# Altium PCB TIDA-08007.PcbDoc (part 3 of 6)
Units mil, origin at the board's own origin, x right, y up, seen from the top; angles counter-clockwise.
Board outline 4212.6 x 2047.24 mil, 10 copper layers (Top Layer, GND 1, Signal Layer 1, GND 2, Split PWR 1, Split PWR 2, GND 3, Signal Layer 2, GND 4, Bottom Layer), stack 66.4 mil thick; 291 components, 178 nets, 1281 pads, 873 vias.
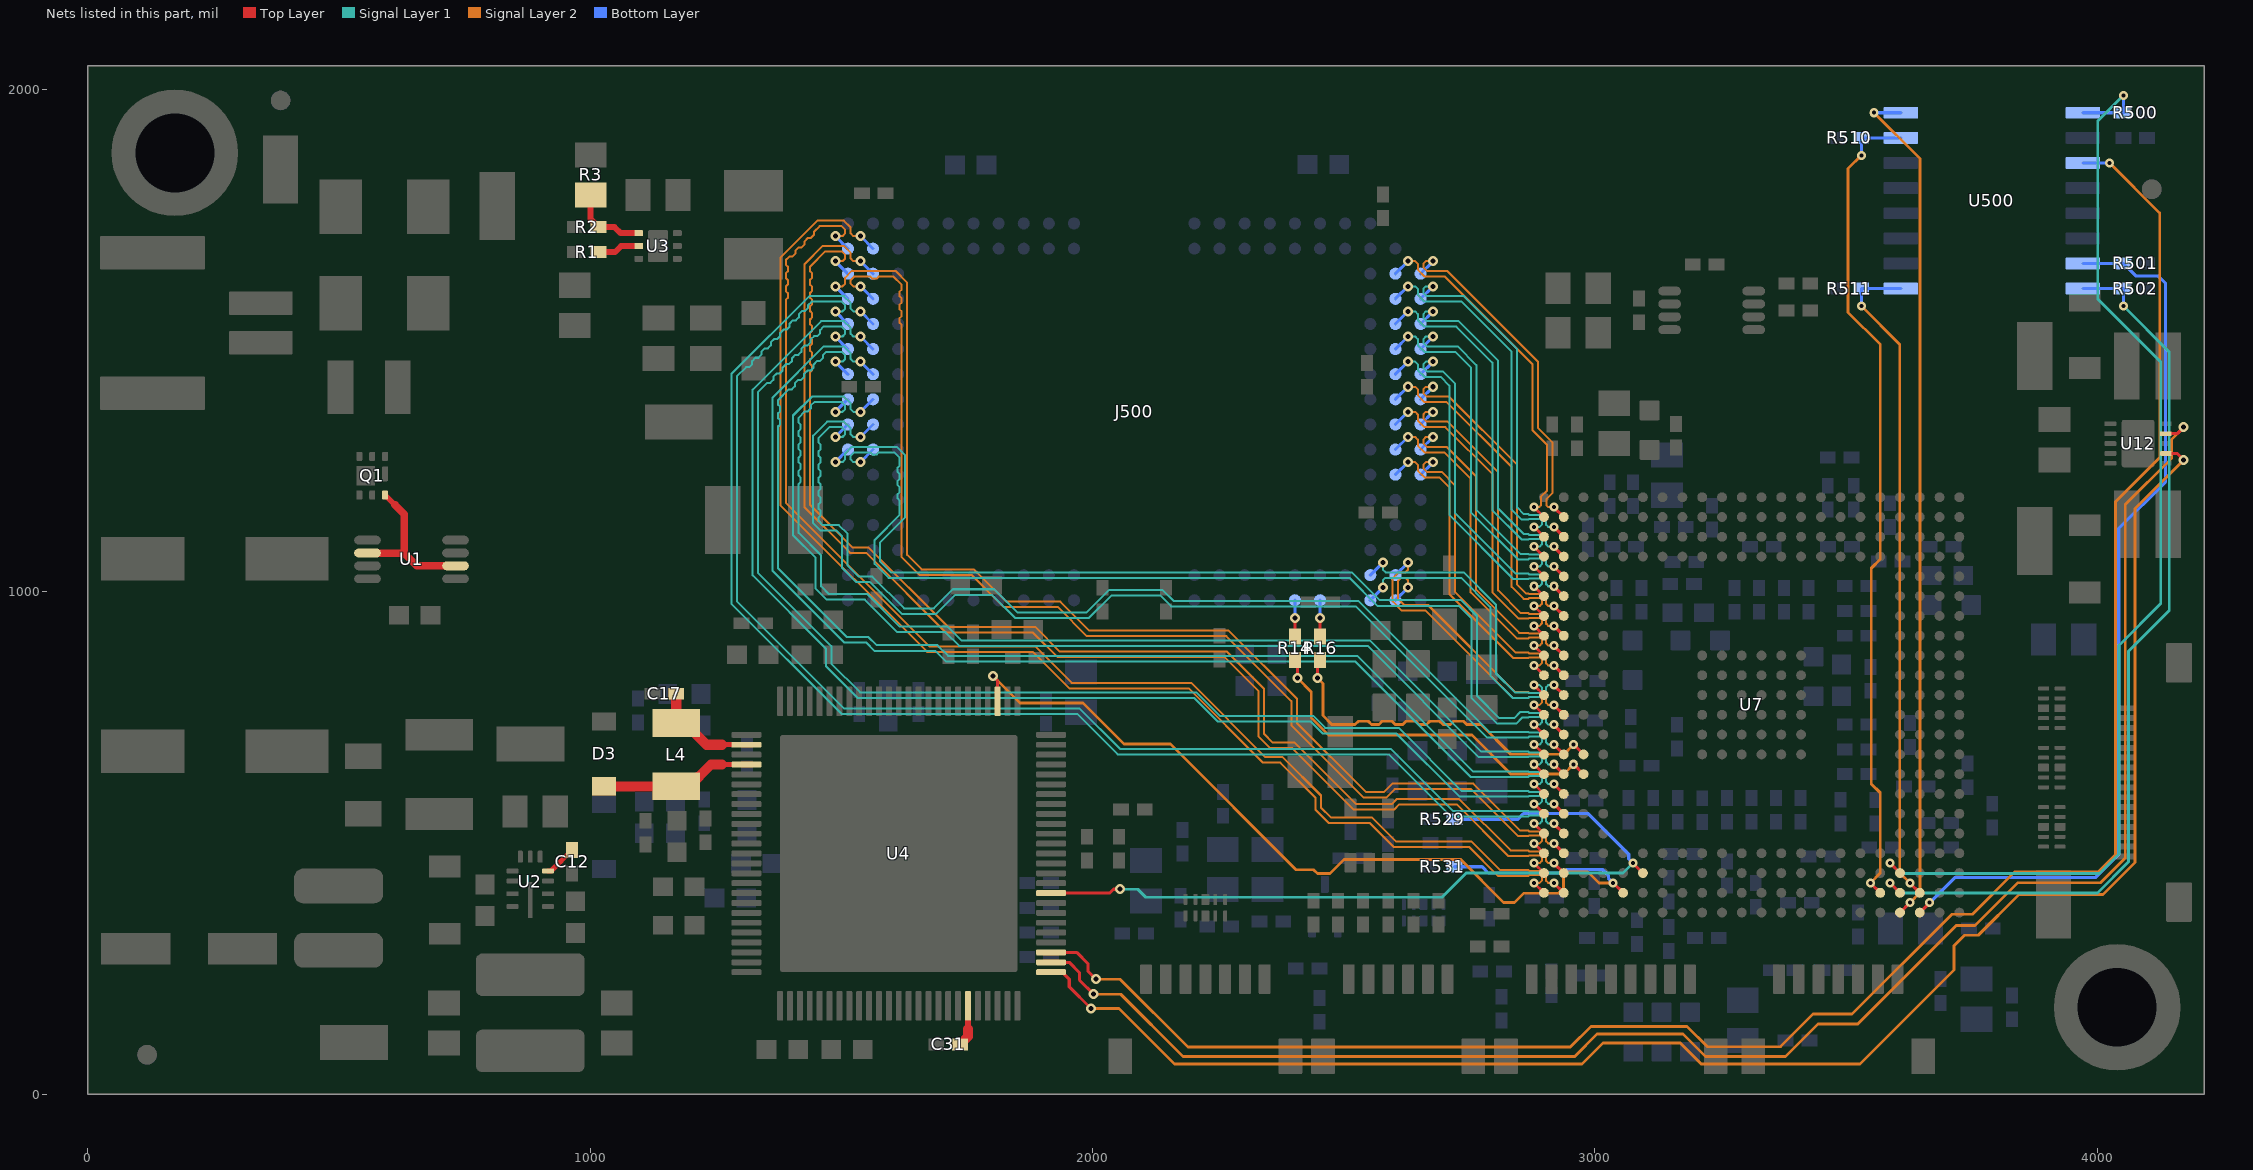
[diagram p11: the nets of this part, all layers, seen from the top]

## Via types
v1: diameter 20, hole 10, Top Layer to Bottom Layer, tented both sides, 439 vias
v2: diameter 18, hole 8, Top Layer to Bottom Layer, tented both sides, 335 vias
v3: diameter 19.68, hole 7.87, Top Layer to Bottom Layer, tented both sides, 72 vias
v4: diameter 19.68, hole 7.87, Top Layer to Bottom Layer, tented bottom, 15 vias
v5: diameter 39.37, hole 19.68, Top Layer to Bottom Layer, 12 vias

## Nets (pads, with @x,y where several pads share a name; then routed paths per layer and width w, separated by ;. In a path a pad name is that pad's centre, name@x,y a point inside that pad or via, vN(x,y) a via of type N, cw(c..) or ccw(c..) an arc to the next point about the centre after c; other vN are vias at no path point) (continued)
\PMIC_SPI_CS0: R531.1 U4.28 U7.E2 | length 1912.4
  Top Layer w6.2: v1(1801.48,832.58) 1811.02,823.04 U4.28@1811.02,782.46 ; v2(3036.21,420.75) U7.E2@3055.9,401.07
  Signal Layer 2 w5.6: v1(1801.48,832.58) 1855.35,778.71 1980.84,778.71 2062.33,697.22 2154.98,697.22 2405.08,447.12 2439.88,447.12 2447.45,439.55 2472.76,439.55 2500.57,467.36 2732.66,467.36 2818.05,381.97 2840.02,381.97 2858.44,400.38 2927.21,400.38 2937.36,410.54 2937.36,432.89 2947.11,442.64 2985.87,442.64 3007.75,420.75 v2(3036.21,420.75)
  Bottom Layer w6.2: R531.1@2720.05,452.95 2775.24,452.95 2787.85,440.34 2937.19,440.34 2944.6,447.76 3014.55,447.76 3026.55,435.75 3026.55,430.42 v2(3036.21,420.75)
\RESET: R529.2 U4.9 U7.F3 | length 1630.7
  Top Layer w6.2: U4.9@1917.32,400.57 2033.77,400.57 2041.46,408.26 v1(2054.23,408.26) ; v2(3075.58,460.12) U7.F3@3095.27,440.44
  Signal Layer 1 w5.6: v1(2054.23,408.26) 2089.8,408.26 2105.89,392.18 2695.54,392.18 2743.86,440.49 3055.95,440.49 v2(3075.58,460.12)
  Bottom Layer w6.2: R529.2@2720.05,547.42 2846.22,547.42 2857.41,558.61 2986.78,558.61 3067.28,478.12 3067.28,468.43 v2(3075.58,460.12)
\S: R501.1 U7.Y1 U500.7 | length 1800
  Top Layer w6.2: U7.Y1@3646.45,361.7 v2(3666.13,381.38)
  Bottom Layer w6.2: v2(3666.13,381.38) 3716.08,431.34 3995.9,431.34 4042.46,477.9 4042.46,1126.34 4135.77,1219.65 4135.77,1613.9 4121.17,1628.5 4077.1,1628.5 R501.1@4051.79,1653.81 U500.7@3971.08,1653.81
ADC_VREF: C31.1 U4.95 | length 83.4
  Top Layer w11.81: 1751.97,129.83 U4.95@1751.97,176.16
  Top Layer w20: C31.1@1736.22,99.29 1751.97,115.03 1751.97,129.83
BST: C12.1 U2.4 | length 65.3
  Top Layer w10: U2.4@916.13,444.51 921.87,444.51 C12.1@964,486.63
C: U7.W1 U500.16 | length 1699.9
  Top Layer w6.2: U7.W1@3607.08,361.7 v2(3626.76,381.38)
  Signal Layer 2 w5.6: v2(3555.43,1953.81) 3646.87,1862.37 3646.87,401.5 v2(3626.76,381.38)
  Bottom Layer w6.2: v2(3555.43,1953.81) U500.16@3608.88,1953.81
COMP: R1.2 U3.2 | length 85.1
  Top Layer w11.81: R1.2@1016.43,1676.5 1049.67,1676.5 1061.67,1688.5 U3.2@1096.61,1688.5
DMD_HS0_CLK_N: J500.G2 U7.A17 | length 694.1
  Top Layer w6.2: v2(2878.73,1011.31) U7.A17@2898.42,991.62
  Signal Layer 1 w4: v1(2627.76,1458.39) 2641.98,1458.39 2647.26,1453.11 2647.26,1441.28 2660.66,1427.89 2692.82,1427.89 2710.11,1410.59 2710.11,1153.28 2837.82,1025.57 2867.29,1025.57 2868.72,1026.99 2891,1026.99 2894.42,1023.58 2894.42,1015.85 2889.87,1011.31 v2(2878.73,1011.31)
  Bottom Layer w6.2: J500.G2@2602.76,1433.39 v1(2627.76,1458.39)
DMD_HS0_CLK_P: J500.G1 U7.B17 | length 689.2
  Top Layer w6.2: v2(2918.1,1011.31) U7.B17@2937.79,991.62
  Signal Layer 1 w4: v1(2677.76,1458.39) 2663.53,1458.39 2658.26,1453.11 2658.26,1445.84 2665.21,1438.89 2697.38,1438.89 2721.11,1415.15 2721.11,1157.83 2842.38,1036.57 2867.4,1036.57 2868.98,1034.99 2894.31,1034.99 2902.42,1026.89 2902.42,1015.85 2906.96,1011.31 v2(2918.1,1011.31)
  Bottom Layer w6.2: J500.G1@2652.76,1433.39 v1(2677.76,1458.39)
DMD_HS0_WDATA0_N: J500.L2 U7.A13 | length 650
  Top Layer w6.2: v2(2878.73,853.83) U7.A13@2898.42,834.14
  Signal Layer 2 w4: v1(2627.76,1258.39) 2641.98,1258.39 2647.26,1253.11 2647.26,1241.28 2660.66,1227.89 2690.12,1227.89 2709.97,1208.03 2709.97,995.85 2837.73,868.09 2867.29,868.09 2868.72,869.51 2891,869.51 2894.42,866.1 2894.42,858.37 2889.87,853.83 v2(2878.73,853.83)
  Bottom Layer w6.2: J500.L2@2602.76,1233.39 v1(2627.76,1258.39)
DMD_HS0_WDATA0_P: J500.L1 U7.B13 | length 645.1
  Top Layer w6.2: v2(2918.1,853.83) U7.B13@2937.79,834.14
  Signal Layer 2 w4: v1(2677.76,1258.39) 2663.53,1258.39 2658.26,1253.11 2658.26,1245.84 2665.21,1238.89 2694.67,1238.89 2720.97,1212.59 2720.97,1000.4 2842.29,879.09 2867.4,879.09 2868.98,877.51 2894.31,877.51 2902.42,869.41 2902.42,858.37 2906.96,853.83 v2(2918.1,853.83)
  Bottom Layer w6.2: J500.L1@2652.76,1233.39 v1(2677.76,1258.39)
DMD_HS0_WDATA1_N: J500.K2 U7.A14 | length 662.4
  Top Layer w6.2: v2(2878.73,893.2) U7.A14@2898.42,873.51
  Signal Layer 2 w4: v1(2627.76,1308.39) 2641.98,1308.39 2647.26,1303.11 2647.26,1291.28 2660.66,1277.89 2699.9,1277.89 2752.58,1225.2 2752.58,999.36 2844.48,907.46 2867.29,907.46 2868.72,908.88 2891,908.88 2894.42,905.47 2894.42,897.74 2889.87,893.2 v2(2878.73,893.2)
  Bottom Layer w6.2: J500.K2@2602.76,1283.39 v1(2627.76,1308.39)
DMD_HS0_WDATA1_P: J500.K1 U7.B14 | length 657.5
  Top Layer w6.2: v2(2918.1,893.2) U7.B14@2937.79,873.51
  Signal Layer 2 w4: v1(2677.76,1308.39) 2663.53,1308.39 2658.26,1303.11 2658.26,1295.84 2665.21,1288.89 2704.45,1288.89 2763.58,1229.75 2763.58,1003.91 2849.04,918.46 2867.4,918.46 2868.98,916.88 2894.31,916.88 2902.42,908.78 2902.42,897.74 2906.96,893.2 v2(2918.1,893.2)
  Bottom Layer w6.2: J500.K1@2652.76,1283.39 v1(2677.76,1308.39)
DMD_HS0_WDATA2_N: J500.J2 U7.A15 | length 672.3
  Top Layer w6.2: v2(2878.73,932.57) U7.A15@2898.42,912.88
  Signal Layer 2 w4: v1(2627.76,1358.39) 2641.98,1358.39 2647.26,1353.11 2647.26,1341.28 2660.66,1327.89 2702.15,1327.89 2796.09,1233.95 2796.09,998.79 2848.04,946.83 2867.29,946.83 2868.72,948.25 2891,948.25 2894.42,944.84 2894.42,937.11 2889.87,932.57 v2(2878.73,932.57)
  Bottom Layer w6.2: J500.J2@2602.76,1333.39 v1(2627.76,1358.39)
DMD_HS0_WDATA2_P: J500.J1 U7.B15 | length 667.4
  Top Layer w6.2: v2(2918.1,932.57) U7.B15@2937.79,912.88
  Signal Layer 2 w4: v1(2677.76,1358.39) 2663.53,1358.39 2658.26,1353.11 2658.26,1345.84 2665.21,1338.89 2706.71,1338.89 2807.09,1238.51 2807.09,1003.35 2852.6,957.83 2867.4,957.83 2868.98,956.25 2894.31,956.25 2902.42,948.15 2902.42,937.11 2906.96,932.57 v2(2918.1,932.57)
  Bottom Layer w6.2: J500.J1@2652.76,1333.39 v1(2677.76,1358.39)
DMD_HS0_WDATA3_N: J500.H2 U7.A16 | length 678.7
  Top Layer w6.2: v2(2878.73,971.94) U7.A16@2898.42,952.25
  Signal Layer 2 w4: v1(2627.76,1408.39) 2641.98,1408.39 2647.26,1403.11 2647.26,1391.28 2660.66,1377.89 2704.84,1377.89 2834.06,1248.66 2834.06,1010.11 2857.96,986.2 2867.29,986.2 2868.72,987.62 2891,987.62 2894.42,984.21 2894.42,976.48 2889.87,971.94 v2(2878.73,971.94)
  Bottom Layer w6.2: J500.H2@2602.76,1383.39 v1(2627.76,1408.39)
DMD_HS0_WDATA3_P: J500.H1 U7.B16 | length 673.8
  Top Layer w6.2: v2(2918.1,971.94) U7.B16@2937.79,952.25
  Signal Layer 2 w4: v1(2677.76,1408.39) 2663.53,1408.39 2658.26,1403.11 2658.26,1395.84 2665.21,1388.89 2709.39,1388.89 2845.06,1253.22 2845.06,1014.67 2862.52,997.2 2867.4,997.2 2868.98,995.62 2894.31,995.62 2902.42,987.52 2902.42,976.48 2906.96,971.94 v2(2918.1,971.94)
  Bottom Layer w6.2: J500.H1@2652.76,1383.39 v1(2677.76,1408.39)
DMD_HS0_WDATA4_N: J500.F2 U7.A18 | length 716.6
  Top Layer w6.2: v2(2878.73,1050.68) U7.A18@2898.42,1030.99
  Signal Layer 1 w4: v1(2627.76,1508.39) 2641.98,1508.39 2647.26,1503.11 2647.26,1491.28 2660.66,1477.89 2722.01,1477.89 2752.9,1446.99 2752.9,1158.84 2846.8,1064.94 2867.29,1064.94 2868.72,1066.36 2891,1066.36 2894.42,1062.95 2894.42,1055.22 2889.87,1050.68 v2(2878.73,1050.68)
  Bottom Layer w6.2: J500.F2@2602.76,1483.39 v1(2627.76,1508.39)
DMD_HS0_WDATA4_P: J500.F1 U7.B18 | length 711.6
  Top Layer w6.2: v2(2918.1,1050.68) U7.B18@2937.79,1030.99
  Signal Layer 1 w4: v1(2677.76,1508.39) 2663.53,1508.39 2658.26,1503.11 2658.26,1495.84 2665.21,1488.89 2726.56,1488.89 2763.9,1451.55 2763.9,1163.4 2851.36,1075.94 2867.4,1075.94 2868.98,1074.36 2894.31,1074.36 2902.42,1066.26 2902.42,1055.22 2906.96,1050.68 v2(2918.1,1050.68)
  Bottom Layer w6.2: J500.F1@2652.76,1483.39 v1(2677.76,1508.39)
DMD_HS0_WDATA5_N: J500.E2 U7.A19 | length 724.3
  Top Layer w6.2: v2(2878.73,1090.05) U7.A19@2898.42,1070.36
  Signal Layer 1 w4: v1(2627.76,1558.39) 2641.98,1558.39 2647.26,1553.11 2647.26,1541.28 2660.66,1527.89 2724.12,1527.89 2795.58,1456.43 2795.58,1162.55 2853.82,1104.31 2867.29,1104.31 2868.72,1105.73 2891,1105.73 2894.42,1102.32 2894.42,1094.59 2889.87,1090.05 v2(2878.73,1090.05)
  Bottom Layer w6.2: J500.E2@2602.76,1533.39 v1(2627.76,1558.39)
DMD_HS0_WDATA5_P: J500.E1 U7.B19 | length 719.4
  Top Layer w6.2: v2(2918.1,1090.05) U7.B19@2937.79,1070.36
  Signal Layer 1 w4: v1(2677.76,1558.39) 2663.53,1558.39 2658.26,1553.11 2658.26,1545.84 2665.21,1538.89 2728.68,1538.89 2806.58,1460.98 2806.58,1167.11 2858.38,1115.31 2867.4,1115.31 2868.98,1113.73 2894.31,1113.73 2902.42,1105.63 2902.42,1094.59 2906.96,1090.05 v2(2918.1,1090.05)
  Bottom Layer w6.2: J500.E1@2652.76,1533.39 v1(2677.76,1558.39)
DMD_HS0_WDATA6_N: J500.D2 U7.A20 | length 740.9
  Top Layer w6.2: v2(2878.73,1129.42) U7.A20@2898.42,1109.73
  Signal Layer 1 w4: v1(2627.76,1608.39) 2641.98,1608.39 2647.26,1603.11 2647.26,1591.28 2660.66,1577.89 2734.38,1577.89 2833.88,1478.39 2833.88,1163.62 2853.82,1143.68 2867.29,1143.68 2868.72,1145.1 2891,1145.1 2894.42,1141.69 2894.42,1133.96 2889.87,1129.42 v2(2878.73,1129.42)
  Bottom Layer w6.2: J500.D2@2602.76,1583.39 v1(2627.76,1608.39)
DMD_HS0_WDATA6_P: J500.D1 U7.B20 | length 736
  Top Layer w6.2: v2(2918.1,1129.42) U7.B20@2937.79,1109.73
  Signal Layer 1 w4: v1(2677.76,1608.39) 2663.53,1608.39 2658.26,1603.11 2658.26,1595.84 2665.21,1588.89 2738.94,1588.89 2844.88,1482.94 2844.88,1168.18 2858.38,1154.68 2867.4,1154.68 2868.98,1153.1 2894.31,1153.1 2902.42,1145 2902.42,1133.96 2906.96,1129.42 v2(2918.1,1129.42)
  Bottom Layer w6.2: J500.D1@2652.76,1583.39 v1(2677.76,1608.39)
DMD_HS0_WDATA7_N: J500.C2 U7.A21 | length 716.1
  Top Layer w6.2: v2(2878.73,1168.79) U7.A21@2898.42,1149.1
  Signal Layer 2 w4: v1(2627.76,1658.39) 2641.98,1658.39 2647.26,1653.11 2647.26,1641.28 2660.66,1627.89 2700.89,1627.89 2875.67,1453.1 2875.67,1321.39 2904.67,1292.4 2904.67,1201.87 2892.2,1189.4 2892.2,1172.12 2888.86,1168.79 v2(2878.73,1168.79)
  Bottom Layer w6.2: J500.C2@2602.76,1633.39 v1(2627.76,1658.39)
DMD_HS0_WDATA7_P: J500.C1 U7.B21 | length 717.3
  Top Layer w6.2: v2(2918.1,1168.79) U7.B21@2937.79,1149.1
  Signal Layer 2 w4: v1(2677.76,1658.39) 2663.53,1658.39 2658.26,1653.11 2658.26,1645.84 2665.21,1638.89 2705.44,1638.89 2886.67,1457.66 2886.67,1325.95 2915.67,1296.95 2915.67,1197.32 2903.2,1184.85 2903.2,1172.41 2906.82,1168.79 v2(2918.1,1168.79)
  Bottom Layer w6.2: J500.C1@2652.76,1633.39 v1(2677.76,1658.39)
DMD_HS1_CLK_N: J500.F19 U7.A6 | length 2524.7
  Top Layer w6.2: v2(2878.73,578.24) U7.A6@2898.42,558.55
  Signal Layer 1 w4: v1(1537.99,1508.39) 1523.77,1508.39 1518.49,1513.66 1518.49,1525.44 1505.05,1538.89 1459.68,1538.89 1323.42,1402.62 1323.42,1032.91 1468.91,887.41 1468.91,852.57 1532.58,788.9 2202,788.9 2248.77,742.13 2434.54,742.13 2458.41,718.26 2604.53,718.26 2730.42,592.38 2867.17,592.38 2868.72,593.92 2891,593.92 2894.42,590.51 2894.42,582.78 2889.87,578.24 v2(2878.73,578.24)
  Bottom Layer w6.2: v1(1537.99,1508.39) J500.F19@1562.99,1483.39
DMD_HS1_CLK_P: J500.F20 U7.B6 | length 2504
  Top Layer w6.2: v2(2918.1,578.24) U7.B6@2937.79,558.55
  Signal Layer 1 w4: v1(1487.99,1508.39) 1502.21,1508.39 1507.49,1513.66 1507.49,1520.89 1500.49,1527.89 1464.24,1527.89 1457.53,1521.18 1457.53,1515.27 1451.52,1509.26 1445.61,1509.26 1438.9,1502.55 1438.9,1496.64 1432.89,1490.63 1426.98,1490.63 1420.27,1483.92 1420.27,1478.02 1414.26,1472 1408.36,1472 1401.65,1465.3 1401.65,1459.39 1395.64,1453.38 1389.73,1453.38 1383.02,1446.67 1383.02,1440.76 1377.01,1434.75 1371.1,1434.75 1364.39,1428.04 1364.39,1422.14 1358.38,1416.12 1352.47,1416.12 1334.42,1398.07 1334.42,1037.46 1479.91,891.97 1479.91,857.13 1537.14,799.9 2206.56,799.9 2253.33,753.13 2439.09,753.13 2462.96,729.26 2609.09,729.26 2734.97,603.38 2867.52,603.38 2868.98,601.92 2894.31,601.92 2902.42,593.82 2902.42,582.78 2906.96,578.24 v2(2918.1,578.24)
  Bottom Layer w6.2: v1(1487.99,1508.39) J500.F20@1512.99,1483.39
DMD_HS1_WDATA0_N: J500.K19 U7.A10 | length 2027.9
  Top Layer w6.2: v2(2878.73,735.72) U7.A10@2898.42,716.03
  Signal Layer 1 w4: v1(1537.99,1258.39) 1523.77,1258.39 1518.49,1263.66 1518.49,1270.93 1525.45,1277.89 1557.72,1277.89 1561.9,1273.71 1570.4,1273.71 1574.58,1277.89 1605.33,1277.89 1616.05,1267.16 1616.05,1251.41 1611.88,1247.23 1611.88,1238.73 1616.05,1234.55 1616.05,1225.07 1611.88,1220.89 1611.88,1212.39 1616.05,1208.21 1616.05,1198.73 1611.88,1194.55 1611.88,1186.05 1616.05,1181.87 1616.05,1153.21 1566.16,1103.31 1566.16,1055.79 1594.07,1027.89 2511.32,1027.89 2566.76,972.45 2729.2,972.45 2754.09,947.57 2754.09,789.07 2805.2,737.96 2843.46,737.96 2855.49,750 2867.31,750 2868.72,751.4 2891,751.4 2894.42,747.99 2894.42,740.26 2889.87,735.72 v2(2878.73,735.72)
  Bottom Layer w6.2: v1(1537.99,1258.39) J500.K19@1562.99,1283.39
DMD_HS1_WDATA0_P: J500.K20 U7.B10 | length 2045.6
  Top Layer w6.2: v2(2918.1,735.72) U7.B10@2937.79,716.03
  Signal Layer 1 w4: v1(1487.99,1258.39) 1502.21,1258.39 1507.49,1263.66 1507.49,1275.49 1520.89,1288.89 1609.88,1288.89 1627.05,1271.72 1627.05,1148.65 1577.16,1098.76 1577.16,1060.35 1598.62,1038.89 2515.88,1038.89 2571.32,983.45 2733.76,983.45 2765.09,952.12 2765.09,793.63 2809.76,748.96 2838.9,748.96 2850.93,761 2867.38,761 2868.98,759.4 2894.31,759.4 2902.42,751.3 2902.42,740.26 2906.96,735.72 v2(2918.1,735.72)
  Bottom Layer w6.2: v1(1487.99,1258.39) J500.K20@1512.99,1283.39
DMD_HS1_WDATA1_N: J500.J19 U7.A9 | length 2123.4
  Top Layer w6.2: v2(2878.73,696.35) U7.A9@2898.42,676.66
  Signal Layer 1 w4: v1(1537.99,1308.39) 1523.77,1308.39 1518.49,1313.66 1518.49,1325.44 1505.05,1338.89 1471.47,1338.89 1443.68,1311.1 1443.68,1136.72 1458.6,1121.8 1490.46,1121.8 1501.39,1110.87 1501.39,1047.62 1529.7,1019.31 1557.19,1019.31 1620.18,956.32 1688.53,956.32 1726.54,994.33 1799.57,994.33 1845.77,948.13 1992.69,948.13 2037.82,993.26 2134.39,993.26 2156.46,971.19 2524.11,971.19 2784.68,710.63 2867.31,710.63 2868.72,712.03 2891,712.03 2894.42,708.62 2894.42,700.89 2889.87,696.35 v2(2878.73,696.35)
  Bottom Layer w6.2: v1(1537.99,1308.39) J500.J19@1562.99,1333.39
DMD_HS1_WDATA1_P: J500.J20 U7.B9 | length 2102.8
  Top Layer w6.2: v2(2918.1,696.35) U7.B9@2937.79,676.66
  Signal Layer 1 w4: v1(1487.99,1308.39) 1502.21,1308.39 1507.49,1313.66 1507.49,1320.89 1500.49,1327.89 1476.02,1327.89 1454.68,1306.55 1454.68,1297.06 1458.86,1292.88 1458.86,1284.38 1454.68,1280.2 1454.68,1270.72 1458.86,1266.54 1458.86,1258.04 1454.68,1253.86 1454.68,1244.37 1458.86,1240.2 1458.86,1231.7 1454.68,1227.52 1454.68,1218.03 1458.86,1213.86 1458.86,1205.35 1454.68,1201.18 1454.68,1191.69 1458.86,1187.51 1458.86,1179.01 1454.68,1174.83 1454.68,1165.35 1458.86,1161.17 1458.86,1152.67 1454.68,1148.49 1454.68,1141.28 1463.16,1132.8 1495.02,1132.8 1512.39,1115.43 1512.39,1052.17 1534.26,1030.31 1561.75,1030.31 1624.74,967.32 1683.97,967.32 1721.98,1005.33 1804.13,1005.33 1850.32,959.13 1988.13,959.13 2033.26,1004.26 2138.95,1004.26 2161.01,982.19 2528.67,982.19 2789.24,721.63 2867.38,721.63 2868.98,720.03 2894.31,720.03 2902.42,711.93 2902.42,700.89 2906.96,696.35 v2(2918.1,696.35)
  Bottom Layer w6.2: v1(1487.99,1308.39) J500.J20@1512.99,1333.39
DMD_HS1_WDATA2_N: J500.H19 U7.A8 | length 2207.7
  Top Layer w6.2: v2(2878.73,656.98) U7.A8@2898.42,637.29
  Signal Layer 1 w4: v1(1537.99,1358.39) 1523.77,1358.39 1518.49,1363.66 1518.49,1375.44 1505.05,1388.89 1441.49,1388.89 1403.72,1351.12 1403.72,1113 1448.82,1067.91 1448.82,1006.53 1470.52,984.82 1546.58,984.82 1611.43,919.97 1706.92,919.97 1734.41,892.48 2547.39,892.48 2768.62,671.26 2867.31,671.26 2868.72,672.66 2891,672.66 2894.42,669.25 2894.42,661.52 2889.87,656.98 v2(2878.73,656.98)
  Bottom Layer w6.2: v1(1537.99,1358.39) J500.H19@1562.99,1383.39
DMD_HS1_WDATA2_P: J500.H20 U7.B8 | length 2187.1
  Top Layer w6.2: v2(2918.1,656.98) U7.B8@2937.79,637.29
  Signal Layer 1 w4: v1(1487.99,1358.39) 1502.21,1358.39 1507.49,1363.66 1507.49,1370.89 1500.49,1377.89 1446.05,1377.89 1439.34,1371.18 1439.34,1365.27 1433.33,1359.26 1427.42,1359.26 1414.72,1346.56 1414.72,1337.07 1418.9,1332.9 1418.9,1324.4 1414.72,1320.22 1414.72,1310.73 1418.9,1306.55 1418.9,1298.05 1414.72,1293.88 1414.72,1284.39 1418.9,1280.21 1418.9,1271.71 1414.72,1267.53 1414.72,1258.05 1418.9,1253.87 1418.9,1245.37 1414.72,1241.19 1414.72,1231.7 1418.9,1227.53 1418.9,1219.02 1414.72,1214.85 1414.72,1117.55 1459.82,1072.46 1459.82,1011.08 1475.07,995.82 1551.14,995.82 1615.99,930.97 1711.47,930.97 1738.96,903.48 2551.95,903.48 2773.17,682.26 2867.38,682.26 2868.98,680.66 2894.31,680.66 2902.42,672.56 2902.42,661.52 2906.96,656.98 v2(2918.1,656.98)
  Bottom Layer w6.2: v1(1487.99,1358.39) J500.H20@1512.99,1383.39
DMD_HS1_WDATA3_N: J500.G19 U7.A7 | length 2373.5
  Top Layer w6.2: v2(2878.73,617.61) U7.A7@2898.42,597.92
  Signal Layer 1 w4: v1(1537.99,1458.39) 1523.77,1458.39 1518.49,1463.66 1518.49,1475.44 1505.05,1488.89 1465.27,1488.89 1362.85,1386.46 1362.85,1042.19 1505.72,899.31 1549.19,899.31 1565.6,882.9 1686.59,882.9 1707.81,861.68 2522.26,861.68 2752.19,631.75 2867.17,631.75 2868.72,633.29 2891,633.29 2894.42,629.88 2894.42,622.15 2889.87,617.61 v2(2878.73,617.61)
  Bottom Layer w6.2: v1(1537.99,1458.39) J500.G19@1562.99,1433.39
DMD_HS1_WDATA3_P: J500.G20 U7.B7 | length 2352.8
  Top Layer w6.2: v2(2918.1,617.61) U7.B7@2937.79,597.92
  Signal Layer 1 w4: v1(1487.99,1458.39) 1502.21,1458.39 1507.49,1463.66 1507.49,1470.89 1500.49,1477.89 1469.83,1477.89 1463.12,1471.18 1463.12,1465.27 1457.11,1459.26 1451.2,1459.26 1444.49,1452.55 1444.49,1446.64 1438.48,1440.63 1432.57,1440.63 1425.87,1433.92 1425.87,1428.02 1419.85,1422 1413.95,1422 1407.24,1415.3 1407.24,1409.39 1401.23,1403.38 1395.32,1403.38 1373.85,1381.9 1373.85,1372.42 1378.02,1368.24 1378.02,1359.74 1373.85,1355.56 1373.85,1346.08 1378.02,1341.9 1378.02,1333.4 1373.85,1329.22 1373.85,1046.74 1510.28,910.31 1553.75,910.31 1570.16,893.9 1691.15,893.9 1712.36,872.68 2526.81,872.68 2756.75,642.75 2867.52,642.75 2868.98,641.29 2894.31,641.29 2902.42,633.19 2902.42,622.15 2906.96,617.61 v2(2918.1,617.61)
  Bottom Layer w6.2: v1(1487.99,1458.39) J500.G20@1512.99,1433.39
DMD_HS1_WDATA4_N: J500.E19 U7.A5 | length 2677.2
  Top Layer w6.2: v2(2878.73,538.86) U7.A5@2898.42,519.18
  Signal Layer 1 w4: v1(1537.99,1558.39) 1523.77,1558.39 1518.49,1563.66 1518.49,1575.44 1505.05,1588.89 1436.13,1588.89 1281.02,1433.78 1281.02,976.58 1500.2,757.39 1969.16,757.39 2049.98,676.57 2589.07,676.57 2712.49,553.14 2867.31,553.14 2868.72,554.55 2891,554.55 2894.42,551.14 2894.42,543.41 2889.87,538.86 v2(2878.73,538.86)
  Bottom Layer w6.2: v1(1537.99,1558.39) J500.E19@1562.99,1533.39
DMD_HS1_WDATA4_P: J500.E20 U7.B5 | length 2660.1
  Top Layer w6.2: v2(2918.1,538.86) U7.B5@2937.79,519.18
  Signal Layer 1 w4: v1(1487.99,1558.39) 1502.21,1558.39 1507.49,1563.66 1507.49,1570.89 1500.49,1577.89 1440.68,1577.89 1433.97,1571.18 1433.97,1565.27 1427.96,1559.26 1422.06,1559.26 1415.35,1552.55 1415.35,1546.64 1409.34,1540.63 1403.43,1540.63 1396.72,1533.92 1396.72,1528.02 1390.71,1522 1384.8,1522 1378.09,1515.3 1378.09,1509.39 1372.08,1503.38 1366.17,1503.38 1359.47,1496.67 1359.47,1490.76 1353.45,1484.75 1347.55,1484.75 1340.84,1478.04 1340.84,1472.14 1334.83,1466.12 1328.92,1466.12 1322.21,1459.42 1322.21,1453.51 1316.2,1447.5 1310.29,1447.5 1292.02,1429.22 1292.02,981.13 1504.76,768.39 1973.72,768.39 2054.54,687.57 2593.62,687.57 2717.05,564.14 2867.38,564.14 2868.98,562.55 2894.31,562.55 2902.42,554.45 2902.42,543.41 2906.96,538.86 v2(2918.1,538.86)
  Bottom Layer w6.2: v1(1487.99,1558.39) J500.E20@1512.99,1533.39
DMD_HS1_WDATA5_N: J500.D19 U7.A4 | length 2333.3
  Top Layer w6.2: v2(2878.73,499.49) U7.A4@2898.42,479.81
  Signal Layer 2 w4: v1(1537.99,1608.39) 1523.77,1608.39 1518.49,1613.66 1518.49,1620.93 1525.45,1627.89 1557.72,1627.89 1561.9,1623.71 1570.4,1623.71 1574.58,1627.89 1603.07,1627.89 1619.76,1611.2 1619.76,1601.72 1615.58,1597.54 1615.58,1589.04 1619.76,1584.86 1619.76,1575.37 1615.58,1571.2 1615.58,1562.69 1619.76,1558.52 1619.76,1549.03 1615.58,1544.85 1615.58,1536.35 1619.76,1532.17 1619.76,1069.27 1655.1,1033.93 1758.93,1033.93 1823.23,969.62 1931.31,969.62 1988.77,912.16 2266.23,912.16 2395.79,782.6 2395.79,734.42 2539.78,590.43 2584.49,590.43 2601.41,607.35 2753.48,607.35 2847.06,513.77 2867.31,513.77 2868.72,515.18 2891,515.18 2894.42,511.77 2894.42,504.04 2889.87,499.49 v2(2878.73,499.49)
  Bottom Layer w6.2: v1(1537.99,1608.39) J500.D19@1562.99,1583.39
DMD_HS1_WDATA5_P: J500.D20 U7.B4 | length 2351
  Top Layer w6.2: v2(2918.1,499.49) U7.B4@2937.79,479.81
  Signal Layer 2 w4: v1(1487.99,1608.39) 1502.21,1608.39 1507.49,1613.66 1507.49,1625.49 1520.89,1638.89 1607.63,1638.89 1630.76,1615.76 1630.76,1073.83 1659.65,1044.93 1763.48,1044.93 1827.79,980.62 1935.86,980.62 1993.33,923.16 2270.79,923.16 2406.79,787.16 2406.79,738.97 2544.33,601.43 2579.93,601.43 2596.85,618.35 2758.04,618.35 2851.62,524.77 2867.38,524.77 2868.98,523.18 2894.31,523.18 2902.42,515.08 2902.42,504.04 2906.96,499.49 v2(2918.1,499.49)
  Bottom Layer w6.2: v1(1487.99,1608.39) J500.D20@1512.99,1583.39
DMD_HS1_WDATA6_N: J500.C19 U7.A3 | length 2537
  Top Layer w6.2: v2(2878.73,460.12) U7.A3@2898.42,440.44
  Signal Layer 2 w4: v1(1537.99,1658.39) 1523.77,1658.39 1518.49,1663.66 1518.49,1675.44 1505.05,1688.89 1463.22,1688.89 1426.54,1652.21 1426.54,1168.81 1517.46,1077.89 1549.1,1077.89 1707.69,919.29 1881.1,919.29 1930.28,870.11 2263.03,870.11 2330.11,803.02 2330.11,713.01 2353.91,689.21 2397.65,689.21 2520.15,566.72 2599.94,566.72 2610.46,577.24 2724.63,577.24 2827.46,474.4 2867.31,474.4 2868.72,475.81 2891,475.81 2894.42,472.4 2894.42,464.67 2889.87,460.12 v2(2878.73,460.12)
  Bottom Layer w6.2: v1(1537.99,1658.39) J500.C19@1562.99,1633.39
DMD_HS1_WDATA6_P: J500.C20 U7.B3 | length 2523.4
  Top Layer w6.2: v2(2918.1,460.12) U7.B3@2937.79,440.44
  Signal Layer 2 w4: v1(1487.99,1658.39) 1502.21,1658.39 1507.49,1663.66 1507.49,1670.89 1500.49,1677.89 1467.77,1677.89 1437.54,1647.65 1437.54,1638.16 1441.72,1633.99 1441.72,1625.48 1437.54,1621.31 1437.54,1611.82 1441.72,1607.64 1441.72,1599.14 1437.54,1594.96 1437.54,1585.48 1441.72,1581.3 1441.72,1572.8 1437.54,1568.62 1437.54,1559.14 1441.72,1554.96 1441.72,1546.46 1437.54,1542.28 1437.54,1532.79 1441.72,1528.62 1441.72,1520.11 1437.54,1515.94 1437.54,1506.45 1441.72,1502.27 1441.72,1493.77 1437.54,1489.59 1437.54,1480.11 1441.72,1475.93 1441.72,1467.43 1437.54,1463.25 1437.54,1453.77 1441.72,1449.59 1441.72,1441.09 1437.54,1436.91 1437.54,1173.36 1522.01,1088.89 1553.66,1088.89 1712.25,930.29 1885.66,930.29 1934.84,881.11 2267.58,881.11 2341.11,807.58 2341.11,717.57 2358.47,700.21 2402.2,700.21 2524.7,577.72 2595.38,577.72 2605.91,588.24 2729.18,588.24 2832.02,485.4 2867.38,485.4 2868.98,483.81 2894.31,483.81 2902.42,475.71 2902.42,464.67 2906.96,460.12 v2(2918.1,460.12)
  Bottom Layer w6.2: v1(1487.99,1658.39) J500.C20@1512.99,1633.39
DMD_HS1_WDATA7_N: J500.B19 U7.A2 | length 2627.9
  Top Layer w6.2: v2(2878.73,420.75) U7.A2@2898.42,401.07
  Signal Layer 2 w4: v1(1537.99,1708.39) 1523.77,1708.39 1518.49,1713.66 1518.49,1725.44 1505.05,1738.89 1452.25,1738.89 1378.59,1665.23 1378.59,1172.71 1670.54,880.77 1880.89,880.77 1953.75,807.91 2191.6,807.91 2339.2,660.31 2373.63,660.31 2443.69,590.25 2443.69,566.23 2469.59,540.33 2551.17,540.33 2598.92,492.58 2749.17,492.58 2806.71,435.03 2867.31,435.03 2868.72,436.44 2891,436.44 2894.42,433.03 2894.42,425.3 2889.87,420.75 v2(2878.73,420.75)
  Bottom Layer w6.2: v1(1537.99,1708.39) J500.B19@1562.99,1683.39
DMD_HS1_WDATA7_P: J500.B20 U7.B2 | length 2607.3
  Top Layer w6.2: v2(2918.1,420.75) U7.B2@2937.79,401.07
  Signal Layer 2 w4: v1(1487.99,1708.39) 1502.21,1708.39 1507.49,1713.66 1507.49,1720.89 1500.49,1727.89 1456.81,1727.89 1445.48,1716.55 1445.48,1710.64 1439.46,1704.63 1433.56,1704.63 1426.85,1697.92 1426.85,1692.02 1420.84,1686.01 1414.93,1686.01 1408.22,1679.3 1408.22,1673.39 1402.21,1667.38 1396.3,1667.38 1389.59,1660.67 1389.59,1651.18 1393.77,1647.01 1393.77,1638.5 1389.59,1634.33 1389.59,1624.84 1393.77,1620.66 1393.77,1612.16 1389.59,1607.98 1389.59,1598.5 1393.77,1594.32 1393.77,1585.82 1389.59,1581.64 1389.59,1177.27 1675.1,891.77 1885.45,891.77 1958.31,818.91 2196.16,818.91 2343.76,671.31 2378.18,671.31 2454.69,594.8 2454.69,570.79 2474.15,551.33 2555.73,551.33 2603.48,503.58 2753.72,503.58 2811.27,446.03 2867.38,446.03 2868.98,444.44 2894.31,444.44 2902.42,436.34 2902.42,425.3 2906.96,420.75 v2(2918.1,420.75)
  Bottom Layer w6.2: v1(1487.99,1708.39) J500.B20@1512.99,1683.39
DMD_LS0_CLK_N: J500.R3 U7.A12 | length 602.5
  Top Layer w6.2: v2(2878.73,814.46) U7.A12@2898.42,794.77
  Signal Layer 1 w4: v1(2577.76,1058.39) 2577.76,1044.37 2583.24,1038.89 2738.47,1038.89 2802.93,974.43 2802.93,837.61 2840.35,800.19 2867.29,800.19 2868.72,798.77 2891,798.77 2894.42,802.18 2894.42,809.91 2889.87,814.46 v2(2878.73,814.46)
  Bottom Layer w6.2: J500.R3@2552.76,1033.39 v1(2577.76,1058.39)
DMD_LS0_CLK_P: J500.T3 U7.B12 | length 616
  Top Layer w6.2: v2(2918.1,814.46) U7.B12@2937.79,794.77
  Signal Layer 1 w4: v1(2577.76,1008.39) 2577.76,1022.87 2582.77,1027.89 2733.92,1027.89 2791.93,969.87 2791.93,833.05 2835.8,789.19 2867.4,789.19 2868.98,790.77 2894.31,790.77 2902.42,798.87 2902.42,809.91 2906.96,814.46 v2(2918.1,814.46)
  Bottom Layer w6.2: J500.T3@2552.76,983.39 v1(2577.76,1008.39)
DMD_LS0_RDATA: R16.2 U7.C9 | length 709.9
  Top Layer w6.2: v1(2447.76,828.58) 2447.76,859.33 R16.2@2452.76,864.33 ; v2(2957.47,696.35) U7.C9@2977.16,676.66
  Signal Layer 2 w5.6: v1(2447.76,828.58) 2458.3,818.03 2458.3,753.99 2476.1,736.2 2522.56,736.2 2528.91,742.54 2548.62,742.54 2554.97,736.2 2569.97,736.2 2576.32,742.54 2596.03,742.54 2602.38,736.2 2617.38,736.2 2623.72,742.54 2643.44,742.54 2649.79,736.2 2664.79,736.2 2671.13,742.54 2690.85,742.54 2697.2,736.2 2712.2,736.2 2718.54,742.54 2738.26,742.54 2744.6,736.2 2773.22,736.2 2832.37,677.04 2938.17,677.04 v2(2957.47,696.35)
DMD_LS0_RDATA_S: J500.T5 R16.1 | length 71.8
  Top Layer w6.2: R16.1@2452.76,911.57 v1(2452.76,948.03)
  Bottom Layer w6.2: v1(2452.76,948.03) J500.T5@2452.76,983.39
DMD_LS0_WDATA_N: J500.R2 U7.A11 | length 564.7
  Top Layer w6.2: v2(2878.73,775.09) U7.A11@2898.42,755.4
  Signal Layer 2 w4: v1(2627.76,1058.39) 2627.76,1043.76 2622.88,1038.89 2609.33,1038.89 2597.35,1026.91 2597.35,981.34 2615.75,962.94 2663.07,962.94 2836.66,789.35 2867.29,789.35 2868.72,790.77 2891,790.77 2894.42,787.36 2894.42,779.63 2889.87,775.09 v2(2878.73,775.09)
  Bottom Layer w6.2: J500.R2@2602.76,1033.39 v1(2627.76,1058.39)
DMD_LS0_WDATA_P: J500.T2 U7.B11 | length 541.5
  Top Layer w6.2: v2(2918.1,775.09) U7.B11@2937.79,755.4
  Signal Layer 2 w4: v1(2627.76,1008.39) 2627.76,1023.01 2622.88,1027.89 2613.89,1027.89 2608.35,1022.35 2608.35,985.9 2620.3,973.94 2667.63,973.94 2841.22,800.35 2867.4,800.35 2868.98,798.77 2894.31,798.77 2902.42,790.67 2902.42,779.63 2906.96,775.09 v2(2918.1,775.09)
  Bottom Layer w6.2: J500.T2@2602.76,983.39 v1(2627.76,1008.39)
DMD_LS1_RDATA: R14.2 U7.C8 | length 732.6
  Top Layer w6.2: R14.2@2402.76,864.33 2407.76,859.33 v1(2407.76,828.58) ; v2(2957.47,656.98) U7.C8@2977.16,637.29
  Signal Layer 2 w5.6: v1(2407.76,828.58) 2435.07,801.27 2435.07,749.83 2469.81,715.1 2754.87,715.1 2832.3,637.67 2938.17,637.67 v2(2957.47,656.98)
DMD_LS1_RDATA_S: J500.T6 R14.1 | length 71.8
  Top Layer w6.2: R14.1@2402.76,911.57 v1(2402.76,948.03)
  Bottom Layer w6.2: v1(2402.76,948.03) J500.T6@2402.76,983.39
DQ0: R510.1 U7.V2 U500.15 | length 1650.1
  Top Layer w6.2: v2(3548.02,420.75) U7.V2@3567.71,401.07
  Signal Layer 2 w5.6: v2(3530.14,1869.07) 3503.88,1842.81 3503.88,1556.48 3567.95,1492.41 3567.95,1065.2 3549.85,1047.09 3549.85,617.99 3567.65,600.18 3567.65,440.39 v2(3548.02,420.75)
  Bottom Layer w6.2: v2(3530.14,1869.07) R510.1@3530.14,1903.81 U500.15@3608.88,1903.81
DQ1: R502.1 U7.W2 U500.8 | length 1829.2
  Top Layer w6.2: v2(3587.39,420.75) U7.W2@3607.08,401.07
  Signal Layer 1 w5.6: v2(3587.39,420.75) 3607.17,400.98 3999.94,400.98 4061.97,463.01 4061.97,882.03 4143.08,963.14 4143.08,1477.78 v2(4051.79,1569.07)
  Bottom Layer w6.2: U500.8@3971.08,1603.81 R502.1@4051.79,1603.81 v2(4051.79,1569.07)
DQ2: R511.1 U7.Y2 U500.9 | length 1329.7
  Top Layer w6.2: v2(3626.76,420.75) U7.Y2@3646.45,401.07
  Signal Layer 2 w5.6: v2(3530.14,1569.07) 3606.71,1492.49 3606.71,440.81 v2(3626.76,420.75)
  Bottom Layer w6.2: v2(3530.14,1569.07) R511.1@3530.14,1603.81 U500.9@3608.88,1603.81
DQ3: R500.1 U7.W3 U500.1 | length 2241.1
  Top Layer w6.2: v2(3587.39,460.12) U7.W3@3607.08,440.44
  Signal Layer 1 w5.6: v2(3587.39,460.12) 3607.76,439.75 4004.47,439.75 4042.79,478.08 4042.79,893.7 4126.08,976.99 4126.08,1457.67 4000.68,1583.07 4000.68,1937.45 v2(4051.79,1988.56)
  Bottom Layer w6.2: U500.1@3971.08,1953.81 R500.1@4051.79,1953.81 v2(4051.79,1988.56)
DRST_HS_IND: D3.1 L4.2 U4.54 | length 301.2
  Top Layer w10: 1262.09,656.48 U4.54@1311.02,656.48
  Top Layer w20: D3.1@1027.73,613.17 L4.2@1171.26,613.17 1197,613.17 1240.31,656.48 1262.09,656.48
DRST_LS_IND: C17.1 L4.1 U4.52 | length 215.8
  Top Layer w10: 1262.09,695.85 U4.52@1311.02,695.85
  Top Layer w20: C17.1@1171.26,797.24 L4.1@1171.26,739.15 1188.42,739.15 1231.73,695.85 1262.09,695.85
ENB_1P1V: U4.1 U12.7 | length 3353.3
  Top Layer w6.2: U4.1@1917.32,243.09 1939.6,243.09 1953.46,229.23 1953.46,214.23 v1(1996.87,170.82) ; U12.7@4136.06,1275.64 4158.92,1275.64 v1(4171.77,1262.79)
  Signal Layer 2 w5.6: v1(1996.87,170.82) 2052.63,170.82 2163.12,60.32 2973.81,60.32 3015.72,102.23 3169.63,102.23 3211.54,60.32 3527.29,60.32 3714.57,247.61 3714.57,295.74 3735.38,316.55 3762.78,316.55 3844.24,398.01 4010.97,398.01 4074.59,461.63 4074.59,1165.6 v1(4171.77,1262.79)
ENB_1P8V: U4.2 U12.9 | length 3372.1
  Top Layer w6.2: U4.2@1917.32,262.77 1953.54,262.77 1974.01,242.3 1974.01,227.3 v1(2002.02,199.29) ; U12.9@4136.06,1315.01 4158.92,1315.01 v1(4171.77,1327.86)
  Signal Layer 2 w5.6: v1(2002.02,199.29) 2056.13,199.29 2180.21,75.21 2959.6,75.21 3004.28,119.89 3175.22,119.89 3219.91,75.21 3379.05,75.21 3443.79,139.95 3522.99,139.95 3718.94,335.91 3756.57,335.91 3841.95,421.29 4006.58,421.29 4055.43,470.14 4055.43,1173.86 4147.29,1265.72 4147.29,1303.38 v1(4171.77,1327.86)
ENB_3P3V: U4.3 U500.3 | length 3905.3
  Top Layer w6.2: U4.3@1917.32,282.46 1968.13,282.46 1991.22,259.37 1991.22,244.37 v1(2006.42,229.17)
  Signal Layer 2 w5.6: v1(2006.42,229.17) 2054.58,229.17 2189.71,94.04 2950.86,94.04 2991.76,134.93 3183.23,134.93 3223.3,94.86 3369.08,94.86 3433.93,159.71 3511.57,159.71 3710.38,358.53 3751.2,358.53 3835.86,443.18 4002.42,443.18 4036.27,477.04 4036.27,1179.39 4123.95,1267.06 4123.95,1754.4 v2(4024.53,1853.81)
  Bottom Layer w6.2: U500.3@3971.08,1853.81 v2(4024.53,1853.81)
FB: R2.1 R3.2 U3.1 | length 155.5
  Top Layer w11.81: R3.2@1000.81,1790 1000.81,1741.72 R2.1@1016.43,1726.09 1048.51,1726.09 1060.51,1714.09 U3.1@1096.61,1714.09
GATE: Q1.3 U1.2 U1.6 | length 317
  Top Layer w10: Q1.3@591.7,1192.94 611.44,1173.19
  Top Layer w15: U1.6@556.78,1077.45 629.62,1077.45 ; 611.44,1173.19 629.62,1155.01 629.62,1077.45 ; U1.2@731.98,1051.86 655.21,1051.86 629.62,1077.45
